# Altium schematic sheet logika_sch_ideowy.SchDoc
size A4; SheetNumber: 1; SheetTotal: 2
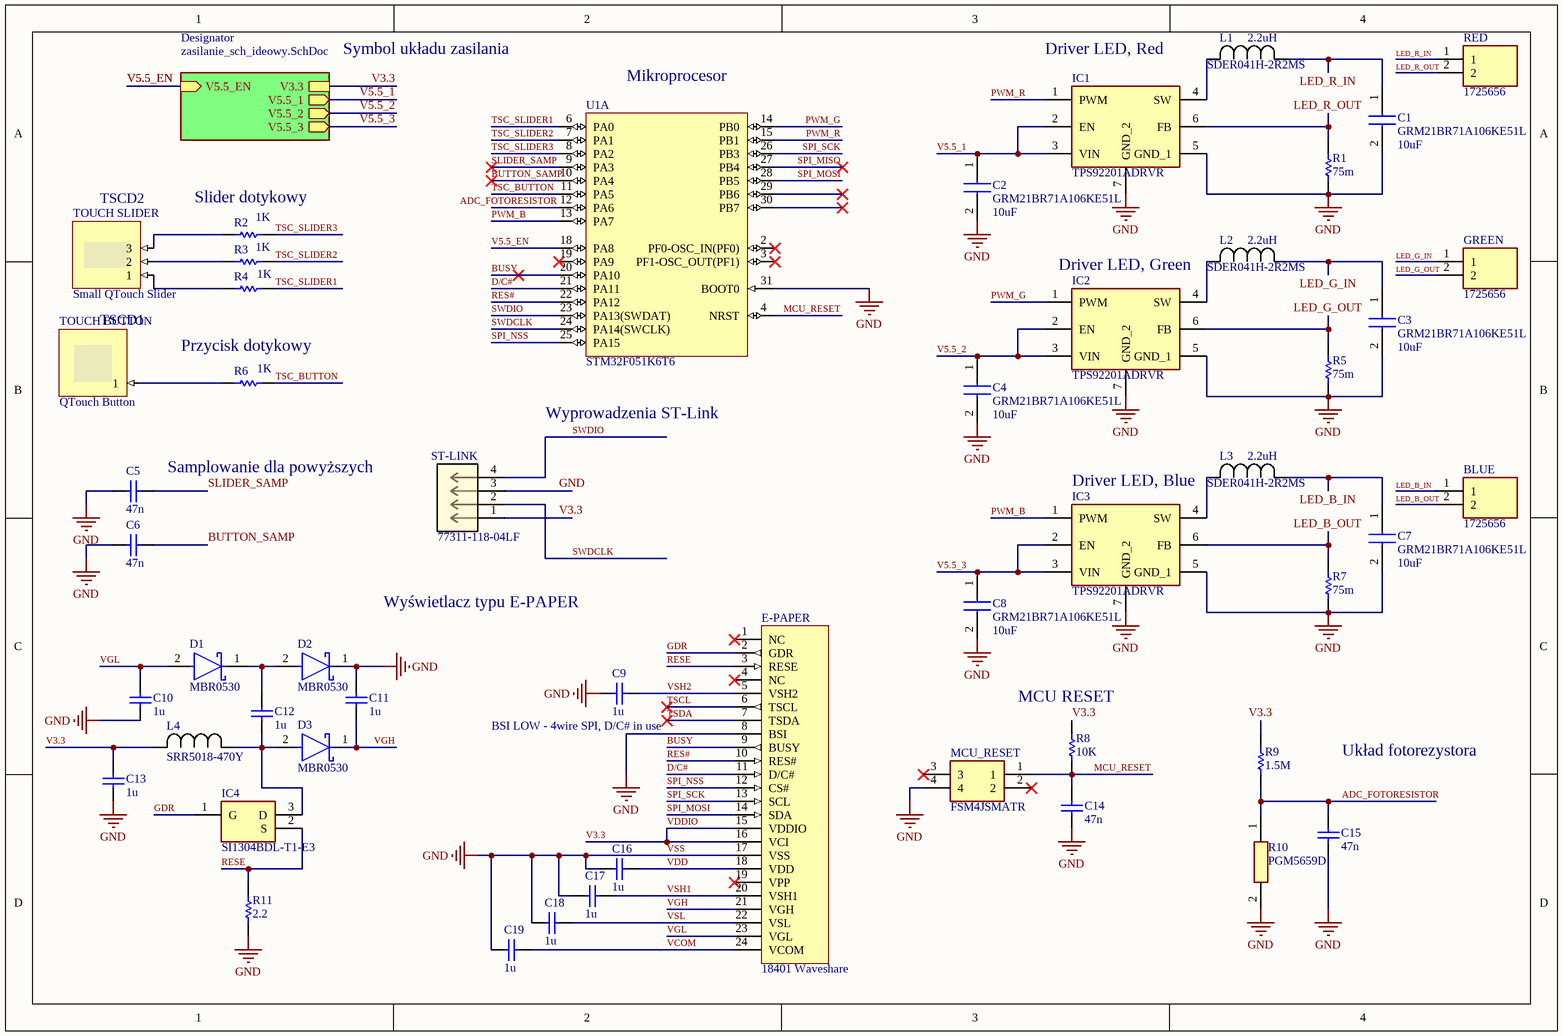
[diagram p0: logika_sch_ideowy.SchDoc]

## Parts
BLUE  1725656  [1725656]
C1  GRM21BR71A106KE51L  Capacitance: 10uF  [CAPC2012X145N]
C2  GRM21BR71A106KE51L  Capacitance: 10uF  [CAPC2012X145N]
C3  GRM21BR71A106KE51L  Capacitance: 10uF  [CAPC2012X145N]
C4  GRM21BR71A106KE51L  Capacitance: 10uF  [CAPC2012X145N]
C5  value 47n  [Capacitor_0805]  (hidden comment: Capacitor)
C6  value 47n  [Capacitor_0805]  (hidden comment: Capacitor)
C7  GRM21BR71A106KE51L  Capacitance: 10uF  [CAPC2012X145N]
C8  GRM21BR71A106KE51L  Capacitance: 10uF  [CAPC2012X145N]
C9  value 1u  [Capacitor_0805]  (hidden comment: Capacitor)
C10  value 1u  [Capacitor_0805]  (hidden comment: Capacitor)
C11  value 1u  [Capacitor_0805]  (hidden comment: Capacitor)
C12  value 1u  [Capacitor_0805]  (hidden comment: Capacitor)
C13  value 1u  [Capacitor_0805]  (hidden comment: Capacitor)
C14  value 47n  [Capacitor_0805]  (hidden comment: Capacitor)
C15  value 47n  [Capacitor_0805]  (hidden comment: Capacitor)
C16  value 1u  [Capacitor_0805]  (hidden comment: Capacitor)
C17  value 1u  [Capacitor_0805]  (hidden comment: Capacitor)
C18  value 1u  [Capacitor_0805]  (hidden comment: Capacitor)
C19  value 1u  [Capacitor_0805]  (hidden comment: Capacitor)
D1  MBR0530  [FP-425-04-MFG]
D2  MBR0530  [FP-425-04-MFG]
D3  MBR0530  [FP-425-04-MFG]
E-PAPER  18401 Waveshare  [18401 Waveshare]
GREEN  1725656  [1725656]
IC1  TPS92201ADRVR  [SON65P200X200X80-7N]
IC2  TPS92201ADRVR  [SON65P200X200X80-7N]
IC3  TPS92201ADRVR  [SON65P200X200X80-7N]
IC4  SI1304BDL-T1-E3  [SOT65P210X110-3N]
L1  SDER041H-2R2MS  value 2.2uH  [IND_SDER041H_CYN]
L2  SDER041H-2R2MS  value 2.2uH  [IND_SDER041H_CYN]
L3  SDER041H-2R2MS  value 2.2uH  [IND_SDER041H_CYN]
L4  SRR5018-470Y  [IND_BOURNS_SRR5018]
MCU_RESET  FSM4JSMATR  [FSM4JSMATR]
R1  value 75m  [Resistor_0805]  (hidden comment: Resistor)
R2  value 1K  [Resistor_0805]  (hidden comment: Resistor)
R3  value 1K  [Resistor_0805]  (hidden comment: Resistor)
R4  value 1K  [Resistor_0805]  (hidden comment: Resistor)
R5  value 75m  [Resistor_0805]  (hidden comment: Resistor)
R6  value 1K  [Resistor_0805]  (hidden comment: Resistor)
R7  value 75m  [Resistor_0805]  (hidden comment: Resistor)
R8  value 10K  [Resistor_0805]  (hidden comment: Resistor)
R9  value 1.5M  [Resistor_0805]  (hidden comment: Resistor)
R10  PGM5659D  [PGM5659D]
R11  value 2.2  [Resistor_0805]  (hidden comment: Resistor)
RED  1725656  [1725656]
ST-LINK  77311-118-04LF  [77311-118-04LF_AMP]
TOUCH_BUTTON  QTouch Button  (no BOM)
TOUCH_SLIDER  Small QTouch Slider  (no BOM)
U1  STM32F051K6T6  [STM-LQFP32_L]  (part A of 2)

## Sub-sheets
Designator = zasilanie_sch_ideowy.SchDoc: V3.3, V5.5_1 (out), V5.5_2 (out), V5.5_3 (out), V5.5_EN (in)

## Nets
GND: C1.2 C2.2 C3.2 C4.2 C5.1 C6.1 C7.2 C8.2 C9.1 C10.1 C11.2 C13.1 C14.1 C15.1 C16.1 C17.1 C18.1 C19.1 D2.1(C) E-PAPER.8(BSI) E-PAPER.17(VSS) IC1.5(GND_1) IC1.7(GND_2) IC2.5(GND_1) IC2.7(GND_2) IC3.5(GND_1) IC3.7(GND_2) MCU_RESET.4 R1.1 R5.1 R7.1 R10.2 R11.1 ST-LINK.3 U1.31(BOOT0)  [also labelled VSS]
ADC_FOTORESISTOR: C15.2 R9.1 R10.1 U1.12(PA6)
BUSY: E-PAPER.9(BUSY) U1.20(PA10)
BUTTON_SAMP: C6.2 U1.10(PA4)
D/C#: E-PAPER.11(D/C#) U1.21(PA11)
GDR: E-PAPER.2(GDR) IC4.1(G)
LED_B_IN: BLUE.1 C7.1 L3.1
LED_B_OUT: BLUE.2 IC3.6(FB) R7.2
LED_G_IN: C3.1 GREEN.1 L2.1
LED_G_OUT: GREEN.2 IC2.6(FB) R5.2
LED_R_IN: C1.1 L1.1 RED.1
LED_R_OUT: IC1.6(FB) R1.2 RED.2
MCU_RESET: C14.2 MCU_RESET.1 R8.1 U1.4(NRST)
PWM_B: IC3.1(PWM) U1.13(PA7)
PWM_G: IC2.1(PWM) U1.14(PB0)
PWM_R: IC1.1(PWM) U1.15(PB1)
RES#: E-PAPER.10(RES#) U1.22(PA12)
RESE: E-PAPER.3(RESE) IC4.2(S) R11.2
SLIDER_SAMP: C5.2 U1.9(PA3)
SPI_MISO: U1.27(PB4)
SPI_MOSI: E-PAPER.14(SDA) U1.28(PB5)
SPI_NSS: E-PAPER.12(CS#) U1.25(PA15)
SPI_SCK: E-PAPER.13(SCL) U1.26(PB3)
SWDCLK: ST-LINK.2 U1.24(PA14(SWCLK))
SWDIO: ST-LINK.4 U1.23(PA13(SWDAT))
TSC_BUTTON: R6.2 U1.11(PA5)
TSC_SLIDER1: R4.2 U1.6(PA0)
TSC_SLIDER2: R3.2 U1.7(PA1)
TSC_SLIDER3: R2.2 U1.8(PA2)
TSCL: E-PAPER.6(TSCL)
TSDA: E-PAPER.7(TSDA)
V3.3: C13.2 E-PAPER.15(VDDIO) E-PAPER.16(VCI) L4.2 R8.2 R9.2 ST-LINK.1 ; sheet Designator/V3.3  [also labelled VDDIO]
V5.5_1: C2.1 IC1.2(EN) IC1.3(VIN) ; sheet Designator/V5.5_1
V5.5_2: C4.1 IC2.2(EN) IC2.3(VIN) ; sheet Designator/V5.5_2
V5.5_3: C8.1 IC3.2(EN) IC3.3(VIN) ; sheet Designator/V5.5_3
V5.5_EN: U1.18(PA8) ; sheet Designator/V5.5_EN
VCOM: C19.2 E-PAPER.24(VCOM)
VDD: C16.2 E-PAPER.18(VDD)
VGH: C11.1 D3.1(C) E-PAPER.21(VGH)
VGL: C10.2 D1.2(A) E-PAPER.23(VGL)
VSH1: C17.2 E-PAPER.20(VSH1)
VSH2: C9.2 E-PAPER.5(VSH2)
VSL: C18.2 E-PAPER.22(VSL)
NetC12_1: C12.1 D3.2(A) IC4.3(D) L4.1
NetC12_2: C12.2 D1.1(C) D2.2(A)
NetIC1_4: IC1.4(SW) L1.2
NetIC2_4: IC2.4(SW) L2.2
NetIC3_4: IC3.4(SW) L3.2
NetR2_1: R2.1 TOUCH_SLIDER.3
NetR3_1: R3.1 TOUCH_SLIDER.2
NetR4_1: R4.1 TOUCH_SLIDER.1
NetR6_1: R6.1 TOUCH_BUTTON.1

Not connected (* = marked no-connect by the designer): E-PAPER 1(NC)* 4(NC)* 19(VPP)*; MCU_RESET 2* 3*; U1 2(PF0-OSC_IN(PF0))* 3(PF1-OSC_OUT(PF1))* 19(PA9)* 29(PB6)* 30(PB7)*

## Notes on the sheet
- Symbol układu zasilania
- (near U1) Mikroprocesor
- Driver LED, Red
- (near TOUCH_SLIDER) TSCD2
- (near R2) Slider dotykowy
- Driver LED, Green
- TSCD1
- (near R6) Przycisk dotykowy
- Wyprowadzenia ST-Link
- (near C5) Samplowanie dla powyższych
- (near L3) Driver LED, Blue
- Wyświetlacz typu E-PAPER
- (near R8) MCU RESET
- (near C9) BSI LOW - 4wire SPI, D/C# in use
- Układ fotorezystora

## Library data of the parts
BLUE GREEN RED = 1725656: 2-pin screw terminal block Connector; Manufacturer_Name: Phoenix Contact
C1-C4 C7 C8 = GRM21BR71A106KE51L: Capacitor, LED DRIVER; Manufacturer_Name: Murata Electronics
C5 C6 C14 C15 = Capacitor: SimulationGenericComponent: True
C9-C12 C17-C19 = Capacitor: Capacitor X5R/X7R, 25V; SimulationGenericComponent: True
C13 C16 = Capacitor: Capacitor X5R/X7R, 6V/25V; SimulationGenericComponent: True
D1-D3 = 1d6ec82d83fb6aee721767c19dac4b9: DIODE SCHOTTKY 30V 500MA SOD123; Polarity: Standard; Max Reverse Leakage Current: 130uA; Forward Voltage: 430mV; Element Configuration: Single; Peak Non-Repetitive Surge Current: 5.5A
E-PAPER = 18401 Waveshare: E-PAPER display; MPN: 18401
IC1-IC3 = TPS92201ADRVR: Integrated Circuit; Manufacturer_Name: Texas Instruments
IC4 = SI1304BDL-T1-E3: Integrated Circuit; Manufacturer_Name: Vishay
L1-L3 = SDER041H-2R2MS: Inductor, LED Driver; Mfr_Name: Cyntec
L4 = SRR5018-470Y: Inductor; Mfr_Name: Bourns Electronics
MCU_RESET = FSM4JSMATR: Switch; Manufacturer_Name: TE Connectivity
R1 R5 R7 = Resistor: Rsense; TC1: 0; SimulationGenericComponent: True
R2-R4 R6 R8 R9 = Resistor: TC1: 0; SimulationGenericComponent: True
R10 = PGM5659D: Resistor; Manufacturer_Name: TOKEN ELECTRONICS INDUSTRY CO LTD
R11 = Resistor: Resistor 0805 1%; TC1: 0; SimulationGenericComponent: True
ST-LINK = 77311-118-04LF: 4-pin male goldpin header; Mfr_Name: Amphenol ICC
TOUCH_BUTTON = QTouchButton: ConfiguratorName: ATMEL_TOUCH; ConfigurationParameters: {}__sensorid[1]{}width[15]{}height[15]{}
TOUCH_SLIDER = SmallQTouchSlider: ConfiguratorName: ATMEL_TOUCH; ConfigurationParameters: {}__sensorid[3]{}width[25]{}height[12]{}gapthickness[0.3]{}
U1 = CMP-0304-00023-2: ARM Cortex-M0 32-bit MCU, 32 KB Flash, 4 KB Internal RAM, 25 I/Os, 32-pin LQFP, -40 to 85 degC, Tray; I/Os (High Current): 25; Operating Frequency(F) (Processor speed) (MHz): 48; FLASH Size (Prog) (kB): 32; Internal RAM Size (kB): 4; Supply Voltage(Vcc) min (V): 2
